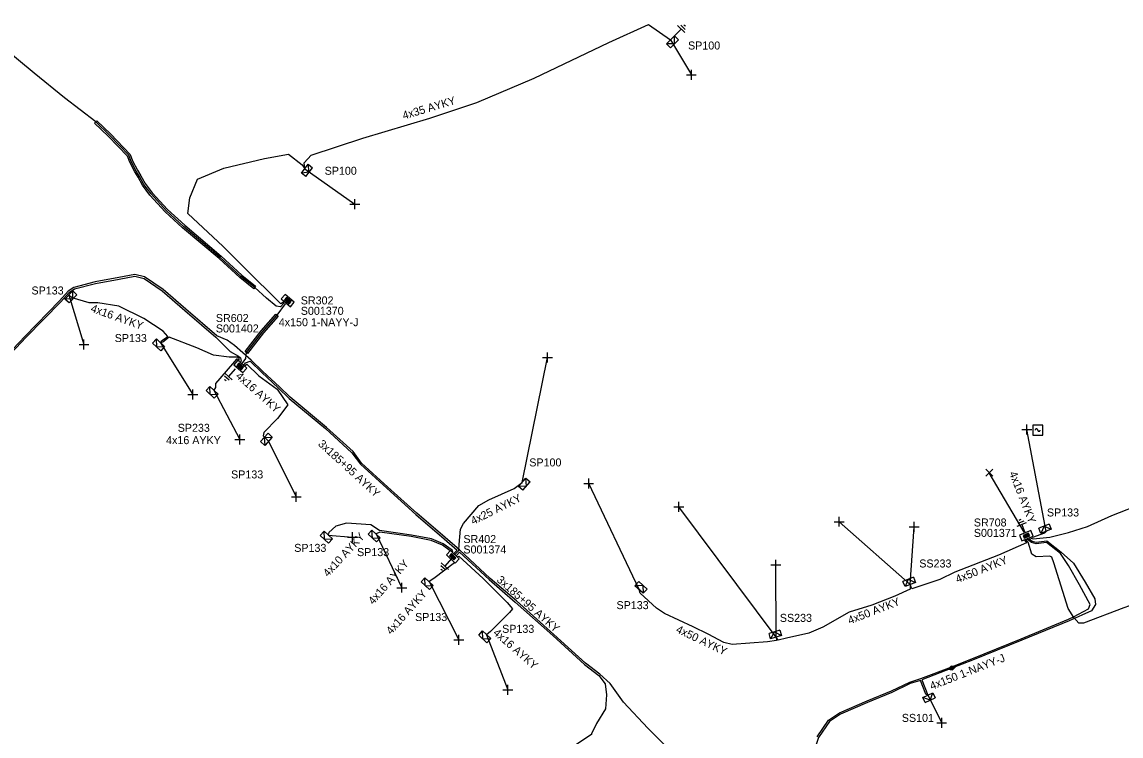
# Model space of a CAD drawing. Extents: x -763093 to -760976, y -1155572 to -1152009.
# Drawn here: x -761822.3 to -761685, y -1155161.8 to -1155072.6 of the extents above; entities that cross this region are included whole.
import ezdxf

# ---------------------------------------------------------------- set-up
doc = ezdxf.new("R2010")
doc.units = 0
for name, color, linetype in [('Vrstva 1', 7, 'Continuous'), ('Vrstva 14', 7, 'Continuous'), ('Vrstva 15', 7, 'Continuous'), ('Vrstva 19', 7, 'Continuous'), ('Vrstva 20', 7, 'Continuous'), ('Vrstva 28', 7, 'Continuous'), ('Vrstva 29', 7, 'Continuous'), ('Vrstva 30', 7, 'Continuous'), ('Vrstva 31', 7, 'Continuous'), ('Vrstva 33', 7, 'Continuous'), ('Vrstva 34', 7, 'Continuous'), ('Vrstva 4', 7, 'Continuous'), ('Vrstva 5', 7, 'Continuous'), ('Vrstva 59', 7, 'Continuous'), ('Vrstva 6', 7, 'Continuous'), ('Vrstva 8', 7, 'Continuous'), ('Vrstva 9', 7, 'Continuous')]:
    doc.layers.add(name, color=color, linetype=linetype)

# ---------------------------------------------------------------- blocks, each defined once
blk = doc.blocks.new('NN870')
at = {"layer": 'Vrstva 4'}
for points in [[(0, -0.25), (0.5, 0), (0, 0.25), (-0.5, 0), (0, -0.25)], [(0.37, 0), (0, 0.19), (-0.36, 0), (0, -0.19), (0.37, 0)], [(0.24, 0), (0, 0.12), (-0.25, 0), (0, -0.12), (0.24, 0)], [(0.12, 0), (0, 0.06), (-0.13, 0), (0, -0.06), (0.12, 0)]]:
    blk.add_lwpolyline(points, dxfattribs=at)
blk = doc.blocks.new('NN800')
at = {"layer": 'Vrstva 1'}
for points in [[(-0.44, 0.44), (0.44, -0.44)], [(-0.44, -0.44), (0.44, 0.44)]]:
    blk.add_lwpolyline(points, dxfattribs=at)
blk = doc.blocks.new('NN620')
at = {"layer": 'Vrstva 8'}
for points in [[(0.75, 0), (-0.75, 0)], [(-0.75, 0), (-0.75, -0.75)], [(0.75, -0.75), (0.75, 0)], [(-0.75, -0.75), (0.75, -0.75)], [(0.37, -0.18), (-0.38, -0.18)], [(-0.38, -0.18), (-0.38, -0.56)], [(-0.38, -0.56), (0.37, -0.56)], [(0.32, -0.23), (-0.33, -0.23)], [(-0.33, -0.23), (-0.33, -0.51)], [(-0.33, -0.51), (0.32, -0.51)], [(0.27, -0.27), (-0.28, -0.27)], [(-0.28, -0.27), (-0.28, -0.46)], [(-0.28, -0.46), (0.27, -0.46)], [(0.23, -0.32), (-0.23, -0.32)], [(-0.23, -0.32), (-0.23, -0.42)], [(-0.23, -0.42), (0.23, -0.42)], [(-0.19, -0.37), (0.19, -0.37)], [(0.23, -0.42), (0.23, -0.32)], [(0.27, -0.46), (0.27, -0.27)], [(0.32, -0.51), (0.32, -0.23)], [(0.37, -0.56), (0.37, -0.18)]]:
    blk.add_lwpolyline(points, dxfattribs=at)
blk = doc.blocks.new('NN630')
at = {"layer": 'Vrstva 9'}
for points in [[(0, -0.7), (-0.7, 0)], [(-0.7, -0.7), (-0.7, 0), (0.7, 0), (0.7, -0.7)], [(-0.7, -0.7), (0.7, -0.7)], [(0, -0.7), (0.7, 0)]]:
    blk.add_lwpolyline(points, dxfattribs=at)
blk = doc.blocks.new('NN810')
at = {"layer": 'Vrstva 14'}
for points in [[(0, -0.64), (0, -1.89)], [(0.63, -1.89), (-0.62, -1.89)], [(0.39, -2.2), (-0.4, -2.2)], [(0, -2.52), (-0.12, -2.52)], [(0.14, -2.52), (0, -2.52)]]:
    blk.add_lwpolyline(points, dxfattribs=at)
blk = doc.blocks.new('NN740')
at = {"layer": 'Vrstva 1'}
for points in [[(0.62, 0.62), (-0.63, 0.62)], [(-0.63, 0.62), (-0.63, -0.63)], [(0, 0), (0, 0.01), (0, 0.03), (-0.01, 0.05), (-0.01, 0.06), (-0.02, 0.08), (-0.03, 0.09), (-0.04, 0.1), (-0.05, 0.11), (-0.06, 0.12), (-0.08, 0.13), (-0.09, 0.14), (-0.11, 0.14), (-0.12, 0.15), (-0.14, 0.15), (-0.15, 0.15), (-0.17, 0.15), (-0.18, 0.15), (-0.2, 0.15), (-0.21, 0.14), (-0.23, 0.13), (-0.24, 0.12), (-0.26, 0.11), (-0.27, 0.1), (-0.28, 0.09), (-0.29, 0.08), (-0.29, 0.06), (-0.3, 0.05), (-0.3, 0.03), (-0.31, 0.02), (-0.31, 0), (-0.31, 0)], [(0.62, -0.63), (0.62, 0.62)], [(-0.63, -0.63), (0.62, -0.63)], [(0, 0), (0, -0.02), (0, -0.03), (0.01, -0.05), (0.01, -0.06), (0.02, -0.08), (0.03, -0.09), (0.04, -0.1), (0.05, -0.11), (0.06, -0.12), (0.07, -0.13), (0.09, -0.14), (0.1, -0.15), (0.12, -0.15), (0.13, -0.15), (0.15, -0.15), (0.16, -0.15), (0.18, -0.15), (0.19, -0.15), (0.21, -0.14), (0.22, -0.14), (0.24, -0.13), (0.25, -0.12), (0.26, -0.11), (0.27, -0.09), (0.28, -0.08), (0.29, -0.07), (0.29, -0.05), (0.3, -0.04), (0.3, -0.02), (0.3, -0.01), (0.3, -0.01)]]:
    blk.add_lwpolyline(points, dxfattribs=at)

msp = doc.modelspace()

# ---------------------------------------------------------------- linework, layer by layer
at = {"layer": 'Vrstva 20'}
for points in [[(-761812.96, -1155084.94), (-761811.25, -1155086.58), (-761808.8, -1155089.13), (-761808.48, -1155089.93), (-761807.87, -1155091.12), (-761807.44, -1155091.8), (-761806.92, -1155092.78), (-761806.03, -1155093.95), (-761804.13, -1155096.03), (-761801.98, -1155097.99), (-761797.42, -1155101.85), (-761794.84, -1155104.23), (-761793.11, -1155105.6), (-761793.35, -1155105.92), (-761795.1, -1155104.53), (-761797.68, -1155102.15), (-761802.24, -1155098.29), (-761804.41, -1155096.31), (-761806.33, -1155094.21), (-761807.26, -1155093), (-761807.78, -1155092), (-761808.21, -1155091.32), (-761808.84, -1155090.09), (-761809.14, -1155089.35), (-761811.53, -1155086.86), (-761813.24, -1155085.22)], [(-761794.43, -1155113.74), (-761792.41, -1155111.15), (-761790.59, -1155109.08), (-761790.29, -1155109.34), (-761792.11, -1155111.41), (-761794.11, -1155113.98)]]:
    msp.add_lwpolyline(points, close=True, dxfattribs=at)
at = {"layer": 'Vrstva 5'}
for points in [[(-761789.65, -1155107.58), (-761789.97, -1155107.81), (-761794.53, -1155103.25), (-761797.17, -1155100.64), (-761801.59, -1155096.53), (-761801.33, -1155094.57), (-761800.37, -1155092.21), (-761797.07, -1155090.87), (-761792.02, -1155089.66), (-761789.02, -1155089.12), (-761787.3, -1155090.45), (-761786.97, -1155090.93), (-761787.05, -1155090.2), (-761786.17, -1155089.25), (-761779.7, -1155087.13), (-761771.35, -1155084.63), (-761765.46, -1155082.64), (-761758.32, -1155079.63), (-761748.98, -1155075.15), (-761744.02, -1155072.9), (-761741.27, -1155074.83)], [(-761789.55, -1155107.67), (-761789.99, -1155108.19), (-761790.53, -1155108.09), (-761791.74, -1155107.11), (-761793.23, -1155105.76), (-761794.97, -1155104.38), (-761797.55, -1155102), (-761802.11, -1155098.14), (-761804.27, -1155096.17), (-761806.18, -1155094.08), (-761807.09, -1155092.89), (-761807.61, -1155091.9), (-761808.04, -1155091.22), (-761808.66, -1155090.01), (-761808.97, -1155089.24), (-761811.39, -1155086.72), (-761813.1, -1155085.08), (-761816.99, -1155082.09), (-761820.8, -1155078.98), (-761824.72, -1155075.73)], [(-761741.37, -1155163.52), (-761744.1, -1155160.8), (-761747.14, -1155157.54), (-761748.82, -1155155.19), (-761750.1, -1155154.06), (-761751.91, -1155152.66), (-761755.84, -1155149.08), (-761760.53, -1155144.89), (-761763.8, -1155142.1), (-761767.64, -1155138.53), (-761769.42, -1155136.99), (-761772.96, -1155133.94), (-761776.59, -1155130.68), (-761779.87, -1155127.7), (-761780.94, -1155126.25), (-761784.25, -1155123.22), (-761788.8, -1155119.46), (-761790.14, -1155118.15), (-761792.2, -1155116.24), (-761793.67, -1155114.83), (-761795.75, -1155112.99), (-761796.67, -1155112.34), (-761797.95, -1155111.8), (-761801.84, -1155108.46), (-761804.68, -1155106.01), (-761806.98, -1155104.44), (-761808.2, -1155104.15), (-761810.19, -1155104.52), (-761813.16, -1155105.04), (-761815.83, -1155105.76), (-761816.55, -1155106.21), (-761817.6, -1155107.41), (-761821.93, -1155111.82), (-761825.78, -1155115.88)], [(-761825.64, -1155116.02), (-761821.79, -1155111.96), (-761817.46, -1155107.55), (-761816.41, -1155106.37), (-761815.75, -1155105.94), (-761813.12, -1155105.24), (-761810.15, -1155104.72), (-761808.2, -1155104.35), (-761807.06, -1155104.62), (-761804.8, -1155106.17), (-761801.98, -1155108.62), (-761798.09, -1155111.96), (-761796.28, -1155113.74), (-761795.24, -1155114.32), (-761795, -1155114.52), (-761794.94, -1155114.97), (-761795.01, -1155115.06)], [(-761795.2, -1155114.91), (-761795.16, -1155114.85), (-761795.19, -1155114.62), (-761795.37, -1155114.47), (-761796.43, -1155114.44), (-761798.38, -1155114.19), (-761800.48, -1155113.31), (-761803.91, -1155111.97), (-761804.71, -1155112.58), (-761805, -1155112.66), (-761804.87, -1155112.43), (-761804.09, -1155111.86), (-761804.68, -1155111.23), (-761807.1, -1155109.63), (-761810.2, -1155108.09), (-761812.85, -1155107.66), (-761813.92, -1155107.68), (-761816.02, -1155107.04), (-761816.45, -1155106.69)], [(-761794.78, -1155115.26), (-761794.35, -1155114.61), (-761794.27, -1155113.86), (-761792.26, -1155111.28), (-761790.44, -1155109.21), (-761789.39, -1155107.78)], [(-761795.31, -1155114.83), (-761795.28, -1155114.8), (-761795.38, -1155114.72), (-761795.51, -1155114.71), (-761796, -1155115.28), (-761798.12, -1155117.74), (-761798.13, -1155118.26), (-761798.32, -1155118.59)], [(-761794.6, -1155115.46), (-761794.37, -1155115.18), (-761793.81, -1155114.97), (-761792.34, -1155116.38), (-761790.3, -1155118.29), (-761788.92, -1155119.62), (-761784.39, -1155123.38), (-761781.08, -1155126.39), (-761779.99, -1155127.82), (-761776.73, -1155130.82), (-761773.1, -1155134.1), (-761769.56, -1155137.15), (-761767.93, -1155138.54), (-761768.32, -1155138.93)], [(-761794.44, -1155115.59), (-761794.23, -1155115.32), (-761792.73, -1155116.79), (-761790.44, -1155118.45), (-761789.09, -1155120.4), (-761790.38, -1155122.12), (-761792.09, -1155123.85), (-761792.17, -1155124.27), (-761791.51, -1155124.95)], [(-761696.32, -1155137), (-761695.96, -1155137.15), (-761693.87, -1155136.93), (-761691.53, -1155136.37), (-761689.19, -1155135.6), (-761686.13, -1155134.23), (-761682.08, -1155132.66), (-761677.94, -1155131.03), (-761674.7, -1155129.42), (-761673.3, -1155128.79), (-761670.35, -1155127.58), (-761668.22, -1155127.03), (-761665.2, -1155126.24), (-761662.56, -1155125.16), (-761659.82, -1155123.93), (-761656, -1155122.45), (-761653.49, -1155121.4), (-761651.28, -1155120.66), (-761649.69, -1155119.84), (-761649.55, -1155119.28), (-761649.76, -1155118.68)], [(-761768.17, -1155139.07), (-761767.71, -1155138.6), (-761767.7, -1155137.85), (-761767.51, -1155135.94), (-761767.12, -1155135.23), (-761765.24, -1155132.98), (-761763.96, -1155132.29), (-761760.79, -1155130.86), (-761759.79, -1155130.09)], [(-761768.48, -1155138.79), (-761768.56, -1155138.56), (-761769.67, -1155137.77), (-761771.13, -1155137.14), (-761773.65, -1155136.67), (-761777.65, -1155136.09), (-761778.72, -1155135.41), (-761781.75, -1155135.19), (-761783.11, -1155135.54), (-761783.98, -1155136.34), (-761784.04, -1155136.68)], [(-761768.82, -1155138.62), (-761769.77, -1155137.95), (-761771.19, -1155137.34), (-761773.69, -1155136.87), (-761777.6, -1155136.3), (-761778.06, -1155136.53)], [(-761697.04, -1155137.32), (-761696.78, -1155137.65), (-761700.27, -1155139.18), (-761705.73, -1155141.31), (-761707.61, -1155142.23), (-761711.14, -1155143.37), (-761711.32, -1155142.85), (-761711.34, -1155143.43), (-761713.23, -1155144.32), (-761716.11, -1155145.41), (-761718.96, -1155146.28), (-761722.26, -1155148.17), (-761724.01, -1155148.94), (-761726.8, -1155149.53), (-761727.81, -1155149.8), (-761728.09, -1155149.42), (-761728.01, -1155149.85), (-761729.16, -1155150.02), (-761733.58, -1155150.35), (-761734.6, -1155150.09), (-761736.55, -1155149.04), (-761738.44, -1155148.12), (-761742.04, -1155146.48), (-761743.04, -1155145.8), (-761745.07, -1155143.93), (-761745.2, -1155143.47)], [(-761722.95, -1155161.86), (-761721.55, -1155159.8), (-761720.15, -1155158.85), (-761716.72, -1155157.39), (-761713.68, -1155156.14), (-761711.39, -1155155.03), (-761710, -1155154.6), (-761706.45, -1155153.27), (-761703.61, -1155152.12), (-761697.46, -1155149.62), (-761691.54, -1155147.19), (-761690.92, -1155146.88), (-761689.06, -1155145.88), (-761688.82, -1155145.35), (-761690.15, -1155142.89), (-761691.55, -1155140.46), (-761692.56, -1155138.96), (-761694.3, -1155137.6), (-761695.6, -1155137.75), (-761696.18, -1155137.6), (-761696.71, -1155137.18)], [(-761696.51, -1155137.09), (-761696.08, -1155137.42), (-761695.58, -1155137.55), (-761694.24, -1155137.4), (-761692.44, -1155138.8), (-761690.91, -1155140.19), (-761689.45, -1155142.56), (-761688.24, -1155144.65), (-761688.17, -1155145.34), (-761688.67, -1155146.13), (-761691.46, -1155147.37), (-761697.38, -1155149.8), (-761703.53, -1155152.3), (-761706.13, -1155153.28)], [(-761673.11, -1155142.63), (-761673.44, -1155142.47), (-761674.65, -1155142.38), (-761675.45, -1155142.44), (-761678.27, -1155143.5), (-761684.62, -1155145.77), (-761689.68, -1155147.68), (-761690.24, -1155147.66), (-761690.88, -1155146.97), (-761691.58, -1155145.85), (-761693.37, -1155140.12), (-761693.63, -1155139.43), (-761693.89, -1155139.3), (-761695.59, -1155139.37), (-761696.12, -1155139.05), (-761696.6, -1155137.57), (-761696.87, -1155137.24)], [(-761696.1, -1155136.91), (-761695.98, -1155136.95), (-761694.51, -1155136.38), (-761694.34, -1155136.21)], [(-761768.03, -1155139.21), (-761767.63, -1155138.81), (-761763.94, -1155142.24), (-761760.67, -1155145.05), (-761755.98, -1155149.22), (-761752.03, -1155152.82), (-761750.22, -1155154.22), (-761749.45, -1155155.24), (-761749.26, -1155156.63), (-761749.38, -1155158.36), (-761750.51, -1155160.19), (-761751.15, -1155161.49), (-761751.15, -1155161.57), (-761752.97, -1155162.79), (-761758.24, -1155165.24), (-761762.88, -1155167.52), (-761766.15, -1155169.29), (-761769.04, -1155171), (-761773.34, -1155173.85), (-761777.41, -1155176.55), (-761779.2, -1155177.51), (-761780.99, -1155178.76), (-761781.49, -1155178.78), (-761781.54, -1155178.72)], [(-761768.28, -1155140.14), (-761770.86, -1155142.08), (-761771.44, -1155142.48)], [(-761767.87, -1155139.37), (-761767.73, -1155139.29), (-761764.67, -1155142.08), (-761761.7, -1155145.08), (-761761.03, -1155145.87), (-761761.4, -1155146.35), (-761763.78, -1155148.7), (-761764.25, -1155149.12)], [(-761706.13, -1155153.28), (-761709.86, -1155154.74), (-761709.12, -1155156.66)], [(-761709.12, -1155156.66), (-761709.35, -1155156.53), (-761710.03, -1155154.82), (-761711.31, -1155155.21), (-761713.6, -1155156.32), (-761716.64, -1155157.57), (-761720.05, -1155159.03), (-761721.41, -1155159.94), (-761722.77, -1155161.96), (-761723.3, -1155163.46), (-761723.36, -1155164.83), (-761723.01, -1155166.44), (-761722.1, -1155167.94), (-761720.45, -1155170.46), (-761717.73, -1155173.51), (-761714.02, -1155177.43), (-761710.43, -1155181.17), (-761706.73, -1155185.28), (-761702.92, -1155188.71), (-761700.45, -1155191.04), (-761697.82, -1155193.5), (-761697.67, -1155193.34)]]:
    msp.add_lwpolyline(points, dxfattribs=at)
at = {"layer": 'Vrstva 59'}
for points in [[(-761741.27, -1155074.83), (-761738.67, -1155079.21)], [(-761786.97, -1155090.93), (-761780.71, -1155095.36)], [(-761816.45, -1155106.69), (-761814.56, -1155112.88)], [(-761805, -1155112.66), (-761800.96, -1155119.13)], [(-761759.79, -1155130.09), (-761756.65, -1155114.49)], [(-761798.32, -1155118.59), (-761795.09, -1155124.75)], [(-761694.34, -1155136.21), (-761696.75, -1155123.5)], [(-761791.51, -1155124.95), (-761788.03, -1155131.88)], [(-761697.09, -1155136.31), (-761701.44, -1155128.88)], [(-761745.2, -1155143.47), (-761751.5, -1155130.25)], [(-761728.09, -1155149.42), (-761740.25, -1155133.13)], [(-761711.32, -1155142.85), (-761720.19, -1155135)], [(-761711.32, -1155142.85), (-761710.84, -1155135.65)], [(-761784.04, -1155136.68), (-761781, -1155136.94)], [(-761778.06, -1155136.53), (-761774.84, -1155143.25)], [(-761728.09, -1155149.42), (-761728.1, -1155140.37)], [(-761771.44, -1155142.48), (-761767.71, -1155149.75)], [(-761764.25, -1155149.12), (-761761.59, -1155156)], [(-761709.12, -1155156.66), (-761707.39, -1155160.13)]]:
    msp.add_lwpolyline(points, dxfattribs=at)

# ---------------------------------------------------------------- block references
at = {"layer": 'Vrstva 15'}
for p, rotation in [((-761741.27, -1155074.83), 135.07238054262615), ((-761795.25, -1155115.44), -41.342027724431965), ((-761696.67, -1155137.09), -158.62422217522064), ((-761768.22, -1155139.12), -41.384222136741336)]:
    msp.add_blockref('NN810', p, dxfattribs=dict(at, rotation=rotation))
at = {"layer": 'Vrstva 19', "rotation": 18.213977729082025}
msp.add_blockref('NN870', (-761706.13, -1155153.28), dxfattribs=at)
at = {"layer": 'Vrstva 28'}
for p, rotation in [((-761789.34, -1155107.68), 139.01495841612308), ((-761794.79, -1155115.33), -41.342027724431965), ((-761696.67, -1155137.09), -157.21470783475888), ((-761768.22, -1155139.12), -43.89576425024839)]:
    msp.add_blockref('NN620', p, dxfattribs=dict(at, rotation=rotation))
at = {"layer": 'Vrstva 31'}
for p, rotation in [((-761741.27, -1155074.83), 45.07238039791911), ((-761786.97, -1155090.93), 52.28680279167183), ((-761816.45, -1155106.69), 46.326055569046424), ((-761805, -1155112.66), -43.12212227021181), ((-761798.32, -1155118.59), -43.09084720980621), ((-761791.51, -1155124.95), -131.78613612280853), ((-761759.79, -1155130.09), 49.02422776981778), ((-761694.34, -1155136.21), -157.79053779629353), ((-761784.04, -1155136.68), -42.79872968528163), ((-761778.06, -1155136.53), -42.109370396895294), ((-761771.44, -1155142.48), -42.984211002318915), ((-761745.2, -1155143.47), 137.04765743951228), ((-761711.32, -1155142.85), -158.62422227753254), ((-761764.25, -1155149.12), -43.01529715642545), ((-761728.09, -1155149.42), -163.00378195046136), ((-761709.12, -1155156.66), 24.934750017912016)]:
    msp.add_blockref('NN630', p, dxfattribs=dict(at, rotation=rotation))
at = {"layer": 'Vrstva 34'}
for p, rotation in [((-761738.67, -1155079.21), 45), ((-761780.71, -1155095.36), 45), ((-761814.56, -1155112.88), 45), ((-761756.65, -1155114.49), 45.00000009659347), ((-761800.96, -1155119.13), 45), ((-761696.75, -1155123.5), 45), ((-761795.09, -1155124.75), 45), ((-761751.5, -1155130.25), 45), ((-761788.03, -1155131.88), 45), ((-761740.25, -1155133.13), 45), ((-761720.19, -1155135), 44.99999995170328), ((-761710.84, -1155135.65), 45), ((-761781, -1155136.94), 45), ((-761728.1, -1155140.37), 45.000000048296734), ((-761774.84, -1155143.24), 45.00000009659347), ((-761767.71, -1155149.75), 45), ((-761761.59, -1155156), 45), ((-761707.39, -1155160.13), 44.99999995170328)]:
    msp.add_blockref('NN800', p, dxfattribs=dict(at, rotation=rotation))
for name, p in [('NN740', (-761695.39, -1155123.56)), ('NN800', (-761701.44, -1155128.88))]:
    msp.add_blockref(name, p, dxfattribs=at)

# ---------------------------------------------------------------- texts
at = {"layer": 'Vrstva 29'}
for s, p in [('S001370', (-761787.47, -1155109.17)), ('S001402', (-761798.08, -1155111.37)), ('S001371', (-761703.37, -1155136.9)), ('S001374', (-761767.15, -1155138.97))]:
    msp.add_text(s, height=1, dxfattribs=at).set_placement(p)
at = {"layer": 'Vrstva 30'}
for s, p in [('SR302', (-761787.47, -1155107.87)), ('SR602', (-761798.08, -1155110.07)), ('SR708', (-761703.37, -1155135.6)), ('SR402', (-761767.15, -1155137.67))]:
    msp.add_text(s, height=1, dxfattribs=at).set_placement(p)
at = {"layer": 'Vrstva 33'}
for s, p in [('SP100', (-761739.08, -1155076.04)), ('SP100', (-761784.49, -1155091.68)), ('SP133', (-761821.12, -1155106.63)), ('SP133', (-761810.72, -1155112.57)), ('SP233', (-761802.85, -1155123.78)), ('SP100', (-761758.92, -1155128.1)), ('SP133', (-761796.18, -1155129.6)), ('SP133', (-761694.24, -1155134.35)), ('SP133', (-761788.29, -1155138.77)), ('SP133', (-761780.44, -1155139.3)), ('SS233', (-761710.19, -1155140.72)), ('SP133', (-761748.02, -1155145.92)), ('SP133', (-761773.19, -1155147.4)), ('SS233', (-761727.61, -1155147.51)), ('SP133', (-761762.31, -1155148.88)), ('SS101', (-761712.37, -1155160))]:
    msp.add_text(s, height=1, dxfattribs=at).set_placement(p)
at = {"layer": 'Vrstva 6'}
for s, rotation, p in [('4x35 AYKY', 16.668, (-761774.6, -1155084.79)), ('4x16 AYKY', 340.413, (-761813.81, -1155108.75)), ('4x16 AYKY', 318.35, (-761795.68, -1155116.94)), ('4x16 AYKY', 359.99, (-761804.3, -1155125.32)), ('3x185+95 AYKY', 317.619, (-761785.39, -1155125.4)), ('4x16 AYKY', 291.384, (-761698.98, -1155128.94)), ('4x25 AYKY', 26.449, (-761765.93, -1155135.42)), ('4x10 AYKY', 47.178, (-761784.07, -1155141.97)), ('4x16 AYKY', 48.626, (-761778.41, -1155145.43)), ('4x50 AYKY', 21.648, (-761705.42, -1155142.69)), ('3x185+95 AYKY', 318.626, (-761763.08, -1155142.39)), ('4x16 AYKY', 48.252, (-761776.18, -1155149.17)), ('4x50 AYKY', 21.325, (-761718.88, -1155147.84)), ('4x50 AYKY', 334.49, (-761740.68, -1155148.78)), ('4x16 AYKY', 318.651, (-761763.52, -1155149)), ('4x150 1-NAYY-J', 21.376, (-761708.64, -1155156.03))]:
    msp.add_text(s, height=1, rotation=rotation, dxfattribs=at).set_placement(p)
msp.add_text('4x150 1-NAYY-J', height=1, dxfattribs=at).set_placement((-761790.22, -1155110.59))

doc.saveas('drawing.dxf')
